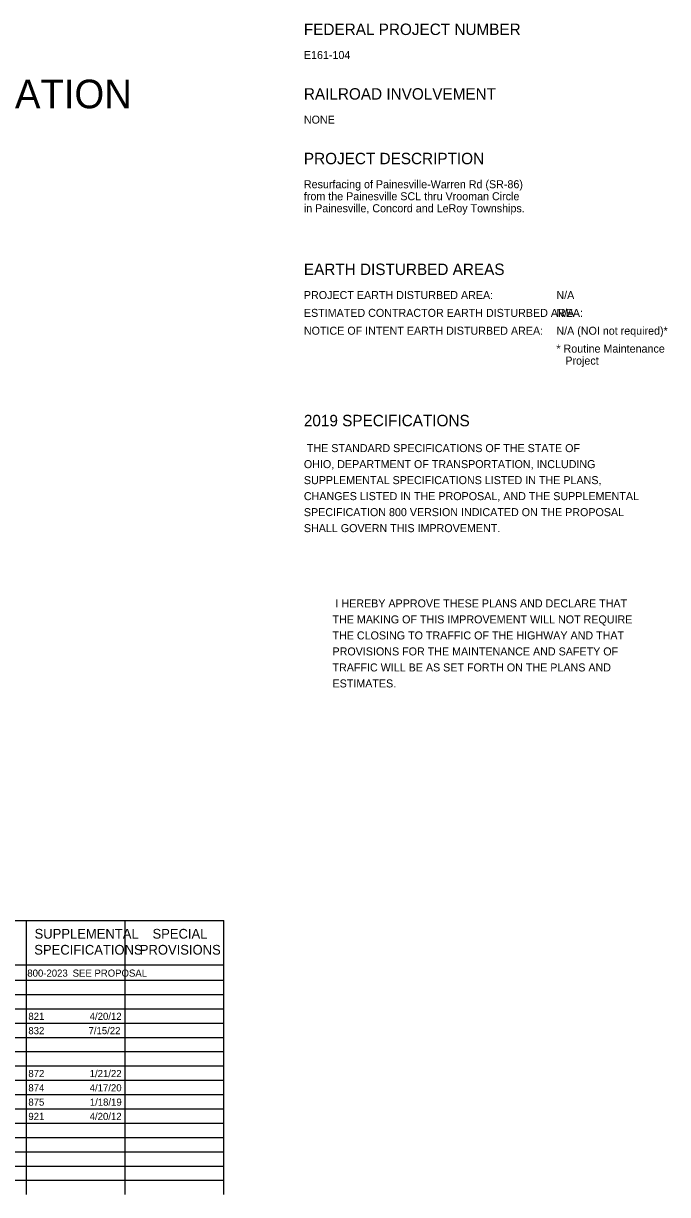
# Model space of a CAD drawing. Extents: x -59 to 82, y -3 to 49.
# Drawn here: x -36.9 to -25.64, y 28.89 to 49.37 of the extents above; entities that cross this region are included whole.
import ezdxf

# ---------------------------------------------------------------- set-up
doc = ezdxf.new("R2010")
doc.units = 0
doc.layers.add('SH_Data', color=7, linetype='Continuous')
doc.layers.add('SH_Text', color=7, linetype='Continuous')

msp = doc.modelspace()

# ---------------------------------------------------------------- linework, layer by layer
at = {"layer": 'SH_Data'}
for p, q in [((-46.848, 33.683), (-33.398, 33.683)), ((-36.848, 28.891), (-36.848, 33.683)), ((-35.123, 28.891), (-35.123, 33.683)), ((-33.398, 28.891), (-33.398, 33.683)), ((-46.848, 32.912), (-33.398, 32.912)), ((-46.848, 32.641), (-33.398, 32.641)), ((-46.848, 32.391), (-33.398, 32.391)), ((-46.848, 32.141), (-33.398, 32.141)), ((-46.848, 31.891), (-33.398, 31.891)), ((-46.848, 31.641), (-33.398, 31.641)), ((-46.848, 31.391), (-33.398, 31.391)), ((-46.848, 31.141), (-33.398, 31.141)), ((-46.848, 30.891), (-33.398, 30.891)), ((-46.848, 30.641), (-33.398, 30.641)), ((-46.848, 30.391), (-33.398, 30.391)), ((-46.848, 30.141), (-33.398, 30.141)), ((-46.848, 29.891), (-33.398, 29.891)), ((-46.848, 29.641), (-33.398, 29.641)), ((-46.848, 29.391), (-33.398, 29.391)), ((-46.848, 29.141), (-33.398, 29.141))]:
    msp.add_line(p, q, dxfattribs=at)

# ---------------------------------------------------------------- texts
for s, p in [(' I HEREBY APPROVE THESE PLANS AND DECLARE THAT', (-31.498, 39.161)), ('THE MAKING OF THIS IMPROVEMENT WILL NOT REQUIRE', (-31.498, 38.881)), ('THE CLOSING TO TRAFFIC OF THE HIGHWAY AND THAT', (-31.498, 38.601)), ('PROVISIONS FOR THE MAINTENANCE AND SAFETY OF', (-31.498, 38.321)), ('TRAFFIC WILL BE AS SET FORTH ON THE PLANS AND', (-31.498, 38.041)), ('ESTIMATES.', (-31.498, 37.761))]:
    msp.add_text(s, height=0.14, dxfattribs=at).set_placement(p)
at = {"layer": 'SH_Text'}
for s, height, p in [('FEDERAL PROJECT NUMBER', 0.2, (-31.998, 49.172)), ('E161-104', 0.14, (-31.998, 48.752)), ('DEPARTMENT OF TRANSPORTATION', 0.5, (-47.078, 47.891)), ('RAILROAD INVOLVEMENT', 0.2, (-31.998, 48.042)), ('NONE', 0.14, (-31.998, 47.622)), ('PROJECT DESCRIPTION', 0.2, (-31.998, 46.912)), ('Resurfacing of Painesville-Warren Rd (SR-86) ', 0.14, (-31.998, 46.492)), ('from the Painesville SCL thru Vrooman Circle', 0.14, (-31.998, 46.282)), ('in Painesville, Concord and LeRoy Townships.', 0.14, (-31.998, 46.072)), ('EARTH DISTURBED AREAS', 0.2, (-31.998, 44.974)), ('PROJECT EARTH DISTURBED AREA:', 0.14, (-31.998, 44.554)), ('N/A', 0.14, (-27.584, 44.554)), ('ESTIMATED CONTRACTOR EARTH DISTURBED AREA:', 0.14, (-31.998, 44.242)), ('N/A', 0.14, (-27.584, 44.242)), ('NOTICE OF INTENT EARTH DISTURBED AREA:', 0.14, (-31.998, 43.93)), ('N/A (NOI not required)*', 0.14, (-27.584, 43.93)), ('* Routine Maintenance', 0.14, (-27.584, 43.617)), ('   Project', 0.14, (-27.584, 43.407)), ('2019 SPECIFICATIONS', 0.2, (-31.998, 42.329)), (' THE STANDARD SPECIFICATIONS OF THE STATE OF', 0.14, (-31.998, 41.877)), ('OHIO, DEPARTMENT OF TRANSPORTATION, INCLUDING', 0.14, (-31.998, 41.597)), ('SUPPLEMENTAL SPECIFICATIONS LISTED IN THE PLANS,', 0.14, (-31.998, 41.317)), ('CHANGES LISTED IN THE PROPOSAL, AND THE SUPPLEMENTAL', 0.14, (-31.998, 41.037)), ('SPECIFICATION 800 VERSION INDICATED ON THE PROPOSAL', 0.14, (-31.998, 40.757)), ('SHALL GOVERN THIS IMPROVEMENT.', 0.14, (-31.998, 40.477)), ('SUPPLEMENTAL', 0.17, (-36.705, 33.368)), ('SPECIAL', 0.17, (-34.644, 33.368)), ('SPECIFICATIONS', 0.17, (-36.711, 33.088)), ('PROVISIONS', 0.17, (-34.866, 33.088)), ('800-2023', 0.125, (-36.832, 32.702)), ('SEE PROPOSAL', 0.125, (-36.04, 32.702)), ('821', 0.125, (-36.814, 31.946)), ('4/20/12', 0.125, (-35.742, 31.946)), ('832', 0.125, (-36.814, 31.696)), ('7/15/22', 0.125, (-35.762, 31.696)), ('872', 0.125, (-36.814, 30.946)), ('1/21/22', 0.125, (-35.742, 30.946)), ('874', 0.125, (-36.814, 30.696)), ('4/17/20', 0.125, (-35.742, 30.696)), ('875', 0.125, (-36.814, 30.446)), ('1/18/19', 0.125, (-35.74, 30.446)), ('921', 0.125, (-36.814, 30.196)), ('4/20/12', 0.125, (-35.742, 30.196))]:
    msp.add_text(s, height=height, dxfattribs=at).set_placement(p)

doc.saveas('drawing.dxf')
